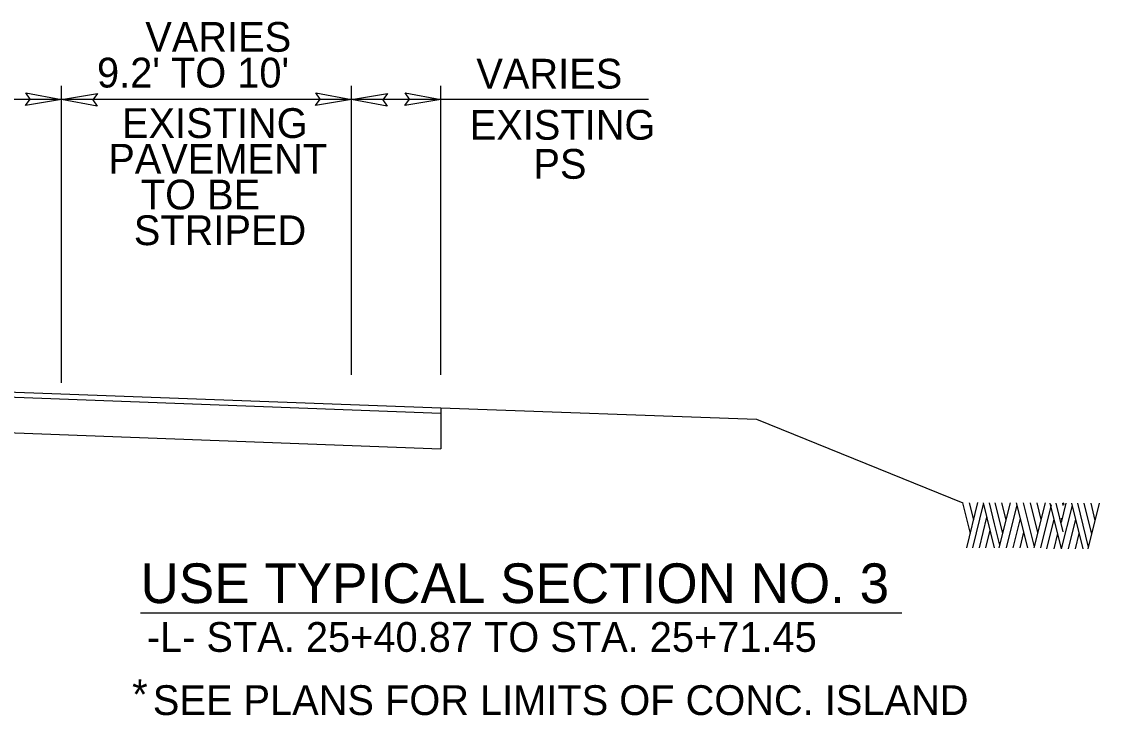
# Model space of a CAD drawing. Extents: x 573748 to 574632, y -54663 to -53209.
# Drawn here: x 573861.7 to 573916.1, y -53533.9 to -53498.9 of the extents above; entities that cross this region are included whole.
import ezdxf

# ---------------------------------------------------------------- set-up
doc = ezdxf.new("R2010")
doc.units = 0
for name, color, linetype in [('Prop Dimension', 7, 'Continuous'), ('Prop Dimension Text', 7, 'Continuous'), ('Prop Terminator CELL', 7, 'Continuous'), ('Typical Pavement Slope CELL', 7, 'Continuous'), ('Typical Text General CELL', 7, 'Continuous')]:
    doc.layers.add(name, color=color, linetype=linetype)

msp = doc.modelspace()

# ---------------------------------------------------------------- linework, layer by layer
at = {"layer": 'Prop Dimension'}
for p, q in [((573863.748, -53517.116), (573863.748, -53502.153)), ((573878.366, -53516.719), (573878.366, -53502.153)), ((573882.866, -53516.719), (573882.866, -53502.153)), ((573863.748, -53502.845), (573844.366, -53502.845)), ((573878.366, -53502.845), (573863.748, -53502.845)), ((573893.339, -53502.845), (573878.366, -53502.845)), ((573832.366, -53516.757), (573882.866, -53518.646)), ((573832.366, -53518.556), (573882.866, -53520.445)), ((573882.866, -53518.389), (573898.789, -53518.96)), ((573882.866, -53518.389), (573882.866, -53520.445)), ((573898.789, -53518.96), (573909.191, -53523.162)), ((573909.573, -53524.712), (573909.191, -53523.162)), ((573909.392, -53525.443), (573909.955, -53523.147)), ((573909.746, -53524.026), (573909.534, -53523.162)), ((573909.695, -53525.443), (573910.242, -53523.229)), ((573910.794, -53525.443), (573910.227, -53523.162)), ((573910.794, -53524.225), (573910.534, -53523.162)), ((573911.211, -53524.69), (573910.829, -53523.162)), ((573911.026, -53525.443), (573911.589, -53523.162)), ((573911.376, -53524.033), (573911.164, -53523.162)), ((573911.392, -53525.443), (573911.931, -53523.266)), ((573912.471, -53525.443), (573911.904, -53523.162)), ((573912.805, -53525.377), (573912.258, -53523.162)), ((573912.979, -53524.668), (573912.609, -53523.162)), ((573912.79, -53525.443), (573913.353, -53523.162)), ((573913.14, -53524.004), (573912.935, -53523.162)), ((573914.168, -53525.48), (573913.597, -53523.192)), ((573914.25, -53524.624), (573913.896, -53523.192)), ((573914.164, -53524.159), (573914.404, -53523.192)), ((573914.25, -53523.302), (573914.227, -53523.192)), ((573914.294, -53523.266), (573914.266, -53523.162)), ((573915.258, -53525.48), (573914.687, -53523.192)), ((573915.534, -53525.406), (573914.986, -53523.192)), ((573915.699, -53524.749), (573915.313, -53523.192)), ((573915.518, -53525.48), (573916.081, -53523.184)), ((573915.868, -53524.063), (573915.656, -53523.192)), ((573913.128, -53525.443), (573913.664, -53523.273)), ((573914.175, -53525.48), (573914.715, -53523.31)), ((573910.03, -53525.443), (573910.408, -53523.886)), ((573911.061, -53525.303), (573910.794, -53524.225)), ((573911.738, -53525.443), (573912.105, -53523.959)), ((573913.435, -53525.48), (573913.797, -53523.996)), ((573914.187, -53524.033), (573914.164, -53523.945)), ((573914.526, -53525.48), (573914.888, -53523.996)), ((573910.349, -53525.443), (573910.569, -53524.543)), ((573912.085, -53525.443), (573912.274, -53524.653)), ((573913.79, -53525.48), (573913.975, -53524.712)), ((573914.88, -53525.48), (573915.065, -53524.712))]:
    msp.add_line(p, q, dxfattribs=at)
at = {"layer": 'Prop Terminator CELL'}
for points in [[(573861.952, -53502.512), (573863.748, -53502.845), (573861.934, -53503.142), (573862.168, -53502.825)], [(573865.545, -53503.179), (573863.748, -53502.845), (573865.563, -53502.549), (573865.328, -53502.866)], [(573876.57, -53502.512), (573878.366, -53502.845), (573876.552, -53503.142), (573876.786, -53502.825)], [(573880.163, -53503.179), (573878.366, -53502.845), (573880.181, -53502.549), (573879.946, -53502.866)], [(573881.07, -53502.512), (573882.866, -53502.845), (573881.052, -53503.142), (573881.286, -53502.825)]]:
    msp.add_lwpolyline(points, close=True, dxfattribs=at)
at = {"layer": 'Typical Pavement Slope CELL'}
msp.add_line((573842.866, -53516.892), (573882.866, -53518.389), dxfattribs=at)
at = {"layer": 'Typical Text General CELL'}
msp.add_line((573867.73, -53528.716), (573906.11, -53528.716), dxfattribs=at)

# ---------------------------------------------------------------- texts
at = {"layer": 'Prop Dimension Text'}
for s, p in [('VARIES', (573867.971, -53500.441)), ("9.2' TO 10'", (573865.536, -53502.241)), ('VARIES', (573884.664, -53502.296)), ('EXISTING', (573866.795, -53504.784)), ('EXISTING', (573884.329, -53504.873)), ('PAVEMENT', (573866.103, -53506.584)), ('PS', (573887.541, -53506.839)), ('TO BE', (573867.745, -53508.384)), ('STRIPED', (573867.393, -53510.184)), ('*', (573867.307, -53533.567))]:
    msp.add_text(s, height=1.5, dxfattribs=at).set_placement(p)
at = {"layer": 'Typical Text General CELL'}
for s, height, p in [('USE TYPICAL SECTION NO. 3', 2, (573867.73, -53528.219)), ('-L- STA. 25+40.87 TO STA. 25+71.45', 1.5, (573868.044, -53530.677)), ('SEE PLANS FOR LIMITS OF CONC. ISLAND', 1.5, (573868.351, -53533.859))]:
    msp.add_text(s, height=height, dxfattribs=at).set_placement(p)

doc.saveas('drawing.dxf')
